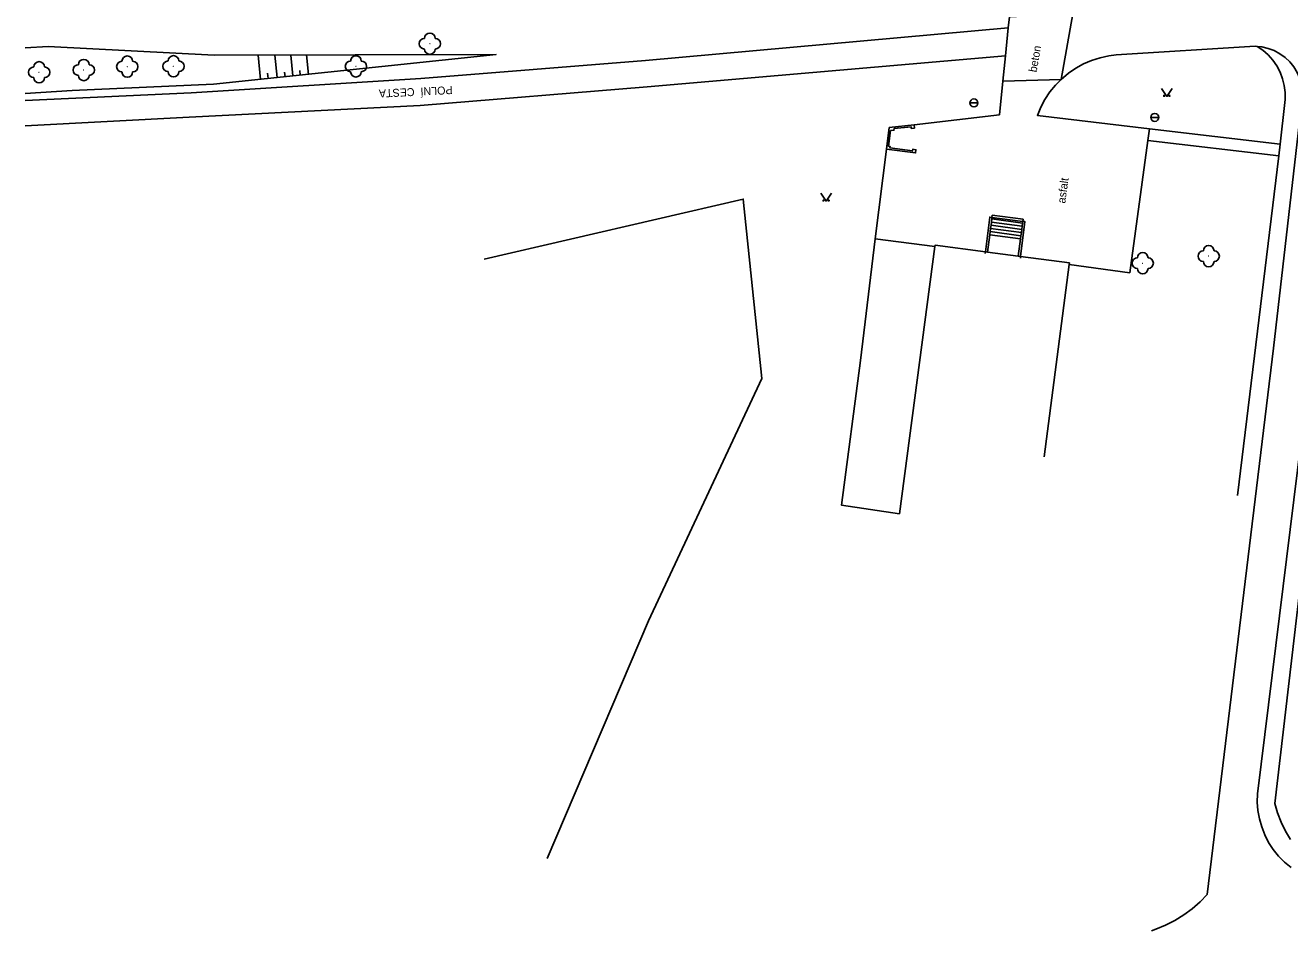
# Model space of a CAD drawing. Extents: x -536391 to -535419, y -1201788 to -1200779.
# Drawn here: x -535851.5 to -535733, y -1201700.2 to -1201615.3 of the extents above; entities that cross this region are included whole.
import ezdxf

# ---------------------------------------------------------------- set-up
doc = ezdxf.new("R2010")
doc.units = 0
for name, color, linetype in [('CIZÍ_PODZEM_POPIS', 7, 'Continuous'), ('DOPLŇ_POPISY', 7, 'Continuous'), ('KONEC_VEDENÍ', 7, 'Continuous'), ('POL_ZNAČKA_PRACOVNÍ', 7, 'Continuous'), ('SDEL_EON', 7, 'Continuous'), ('SDEL_EON_POPIS', 7, 'Continuous'), ('TECH_OCHR_PÁSMO_HRAN', 7, 'Continuous')]:
    doc.layers.add(name, color=color, linetype=linetype)

msp = doc.modelspace()

# ---------------------------------------------------------------- linework, layer by layer
at = {"layer": 'CIZÍ_PODZEM_POPIS'}
for p, q in [((-535762.935, -1201622.56), (-535762.185, -1201622.56)), ((-535745.975, -1201623.91), (-535745.225, -1201623.91))]:
    msp.add_line(p, q, dxfattribs=at)
for points in [[(-535851.47, -1201621.68), (-535847.09, -1201621.4), (-535833.82, -1201620.81), (-535807.34, -1201618.03), (-535833.76, -1201618.08), (-535849.31, -1201617.27), (-535851.47, -1201617.39)], [(-535770.74, -1201626.89), (-535770.49, -1201624.86), (-535768.16, -1201624.61)], [(-535768.16, -1201624.61), (-535768.13, -1201624.91), (-535768.43, -1201624.94), (-535768.44, -1201624.79), (-535770.04, -1201624.96), (-535770.06, -1201625.11), (-535770.37, -1201625.15), (-535770.56, -1201626.61), (-535770.41, -1201626.63), (-535770.43, -1201626.78), (-535768.31, -1201627.05), (-535768.29, -1201626.9), (-535767.99, -1201626.94), (-535768.03, -1201627.24), (-535770.74, -1201626.89)]]:
    msp.add_lwpolyline(points, dxfattribs=at)
for centre in [(-535762.56, -1201622.56), (-535745.6, -1201623.91)]:
    msp.add_circle(centre, 0.375, dxfattribs=at)
at = {"layer": 'DOPLŇ_POPISY'}
for points in [[(-535829.41, -1201620.35), (-535829.65, -1201618.07)], [(-535827.86, -1201620.18), (-535828.08, -1201618.07)], [(-535826.39, -1201620.03), (-535826.59, -1201618.07)], [(-535824.92, -1201619.88), (-535825.11, -1201618.06)], [(-535828.72, -1201620.27), (-535828.77, -1201619.76)], [(-535827.11, -1201620.11), (-535827.16, -1201619.66)], [(-535825.7, -1201619.96), (-535825.74, -1201619.52)]]:
    msp.add_lwpolyline(points, dxfattribs=at)
at = {"layer": 'KONEC_VEDENÍ'}
msp.add_lwpolyline([(-535808.46, -1201637.19), (-535784.18, -1201631.57), (-535782.44, -1201648.38), (-535793.05, -1201671.12), (-535802.54, -1201693.4)], dxfattribs=at)
for centre in [(-535813.55, -1201617), (-535850.17, -1201619.68), (-535845.99, -1201619.47), (-535841.91, -1201619.15), (-535837.58, -1201619.12), (-535820.48, -1201619.13), (-535746.73, -1201637.58), (-535740.55, -1201636.92)]:
    msp.add_circle(centre, 0.0005, dxfattribs=at)
for centre, start, end in [((-535813.55, -1201616.5), 0, 179.99999), ((-535814.05, -1201617), 89.99999, 269.99999), ((-535813.55, -1201617.5), 179.99999, 359.99999), ((-535813.05, -1201617), 270, 89.99999), ((-535850.17, -1201619.18), 0, 179.99999), ((-535845.99, -1201618.97), 0, 179.99999), ((-535842.41, -1201619.15), 89.99999, 269.99999), ((-535841.91, -1201618.65), 0, 179.99999), ((-535841.41, -1201619.15), 270, 89.99999), ((-535838.08, -1201619.12), 89.99999, 269.99999), ((-535837.58, -1201618.62), 0, 179.99999), ((-535837.08, -1201619.12), 270, 89.99999), ((-535820.98, -1201619.13), 89.99999, 269.99999), ((-535820.48, -1201618.63), 0, 179.99999), ((-535819.98, -1201619.13), 270, 89.99999), ((-535850.67, -1201619.68), 89.99999, 269.99999), ((-535849.67, -1201619.68), 270, 89.99999), ((-535846.49, -1201619.47), 89.99999, 269.99999), ((-535845.99, -1201619.97), 179.99999, 359.99999), ((-535845.49, -1201619.47), 270, 89.99999), ((-535841.91, -1201619.65), 179.99999, 359.99999), ((-535837.58, -1201619.62), 179.99999, 359.99999), ((-535820.48, -1201619.63), 179.99999, 359.99999), ((-535850.17, -1201620.18), 179.99999, 359.99999), ((-535746.73, -1201637.08), 0, 179.99999), ((-535741.05, -1201636.92), 89.99999, 269.99999), ((-535740.55, -1201636.42), 0, 179.99999), ((-535740.05, -1201636.92), 270, 89.99999), ((-535747.23, -1201637.58), 89.99999, 269.99999), ((-535746.23, -1201637.58), 270, 89.99999), ((-535740.55, -1201637.42), 179.99999, 359.99999), ((-535746.73, -1201638.08), 179.99999, 359.99999)]:
    msp.add_arc(centre, 0.5, start, end, dxfattribs=at)
at = {"layer": 'SDEL_EON'}
for points in [[(-535744.97, -1201621.19), (-535744.47, -1201621.94), (-535743.97, -1201621.19)], [(-535776.91, -1201631.01), (-535776.41, -1201631.76), (-535775.91, -1201631.01)]]:
    msp.add_lwpolyline(points, dxfattribs=at)
for centre in [(-535744.72, -1201621.89), (-535744.22, -1201621.89), (-535776.66, -1201631.71), (-535776.16, -1201631.71)]:
    msp.add_circle(centre, 0.05, dxfattribs=at)
at = {"layer": 'SDEL_EON_POPIS'}
for points in [[(-535769.52, -1201661.07), (-535766.21, -1201636.03)], [(-535766.21, -1201636.03), (-535766.19, -1201635.9), (-535761.48, -1201636.52)], [(-535761.48, -1201636.52), (-535761.28, -1201636.55)], [(-535761.28, -1201636.55), (-535758.4, -1201636.93)], [(-535758.4, -1201636.93), (-535758.18, -1201636.96)], [(-535758.18, -1201636.96), (-535753.6, -1201637.56), (-535753.62, -1201637.7)], [(-535753.62, -1201637.7), (-535755.97, -1201655.74)]]:
    msp.add_lwpolyline(points, dxfattribs=at)
at = {"layer": 'TECH_OCHR_PÁSMO_HRAN'}
for points in [[(-535759.33, -1201615.52), (-535759.23, -1201614.49), (-535753.27, -1201614.2)], [(-535753.27, -1201614.2), (-535754.38, -1201620.36)], [(-535759.33, -1201615.52), (-535793.35, -1201618.58), (-535814.41, -1201620.27), (-535835.91, -1201621.61), (-535851.47, -1201622.34)], [(-535759.6, -1201618.13), (-535759.33, -1201615.52)], [(-535754.38, -1201620.36), (-535753.69, -1201619.77), (-535753.01, -1201619.3), (-535752.28, -1201618.9), (-535751.52, -1201618.57), (-535750.73, -1201618.32), (-535749.91, -1201618.15), (-535749.22, -1201618.06), (-535736.18, -1201617.24), (-535736, -1201617.26)], [(-535736, -1201617.26), (-535735.58, -1201617.3), (-535734.99, -1201617.44), (-535734.42, -1201617.65), (-535733.89, -1201617.94), (-535733.39, -1201618.29), (-535732.95, -1201618.71), (-535732.57, -1201619.18), (-535732.25, -1201619.69), (-535732.01, -1201620.25), (-535731.84, -1201620.83), (-535731.74, -1201621.43), (-535731.73, -1201621.59), (-535734.49, -1201645.56), (-535740.68, -1201696.76), (-535741.36, -1201697.46), (-535742.1, -1201698.11), (-535742.89, -1201698.69), (-535743.72, -1201699.21), (-535744.59, -1201699.66), (-535745.5, -1201700.03), (-535745.91, -1201700.17)], [(-535733.86, -1201626.41), (-535733.41, -1201622.53), (-535733.38, -1201622.24), (-535733.38, -1201621.58), (-535733.46, -1201620.93), (-535733.62, -1201620.29), (-535733.85, -1201619.67), (-535734.16, -1201619.09), (-535734.54, -1201618.55), (-535734.97, -1201618.06), (-535735.47, -1201617.62), (-535736, -1201617.26)], [(-535759.6, -1201618.13), (-535793.17, -1201621.05), (-535814.47, -1201622.81), (-535836.12, -1201623.88), (-535851.47, -1201624.71)], [(-535759.84, -1201620.53), (-535759.6, -1201618.13)], [(-535768.16, -1201624.61), (-535760.16, -1201623.67), (-535759.84, -1201620.53)], [(-535754.38, -1201620.36), (-535759.84, -1201620.53)], [(-535746.11, -1201624.99), (-535756.61, -1201623.72), (-535756.29, -1201622.95), (-535755.9, -1201622.22), (-535755.44, -1201621.53), (-535754.91, -1201620.89), (-535754.38, -1201620.36)], [(-535746.11, -1201624.99), (-535746.26, -1201626.08)], [(-535733.86, -1201626.41), (-535746.11, -1201624.99)], [(-535771.81, -1201635.29), (-535770.74, -1201626.89)], [(-535746.26, -1201626.08), (-535747.95, -1201638.48), (-535753.62, -1201637.7)], [(-535733.99, -1201627.51), (-535746.26, -1201626.08)], [(-535733.99, -1201627.51), (-535733.86, -1201626.41)], [(-535733.99, -1201627.51), (-535737.84, -1201659.35)], [(-535760.86, -1201633.29), (-535761.07, -1201633.26), (-535761.48, -1201636.52)], [(-535760.99, -1201634.32), (-535760.95, -1201634.02)], [(-535760.95, -1201634.02), (-535760.91, -1201633.72)], [(-535760.95, -1201634.02), (-535758.07, -1201634.41)], [(-535760.91, -1201633.72), (-535760.88, -1201633.42)], [(-535760.91, -1201633.72), (-535758.03, -1201634.12)], [(-535760.88, -1201633.42), (-535760.86, -1201633.29)], [(-535760.88, -1201633.42), (-535757.99, -1201633.82)], [(-535760.86, -1201633.29), (-535760.84, -1201633.09), (-535757.94, -1201633.46), (-535757.97, -1201633.66)], [(-535757.97, -1201633.66), (-535760.86, -1201633.29)], [(-535758.18, -1201636.96), (-535757.77, -1201633.68), (-535757.97, -1201633.66)], [(-535758.03, -1201634.12), (-535758.07, -1201634.41)], [(-535757.99, -1201633.82), (-535758.03, -1201634.12)], [(-535757.97, -1201633.66), (-535757.99, -1201633.82)], [(-535769.52, -1201661.07), (-535774.96, -1201660.27), (-535773.2, -1201646.69), (-535771.81, -1201635.29)], [(-535766.21, -1201636.03), (-535771.81, -1201635.29)], [(-535761.28, -1201636.55), (-535761.07, -1201634.91)], [(-535761.07, -1201634.91), (-535761.03, -1201634.61)], [(-535761.07, -1201634.91), (-535758.19, -1201635.31)], [(-535761.03, -1201634.61), (-535760.99, -1201634.32)], [(-535761.03, -1201634.61), (-535758.15, -1201635.01)], [(-535760.99, -1201634.32), (-535758.11, -1201634.71)], [(-535758.19, -1201635.31), (-535758.4, -1201636.93)], [(-535758.15, -1201635.01), (-535758.19, -1201635.31)], [(-535758.11, -1201634.71), (-535758.15, -1201635.01)], [(-535758.07, -1201634.41), (-535758.11, -1201634.71)], [(-535761.48, -1201636.52), (-535761.5, -1201636.66)], [(-535758.2, -1201637.1), (-535758.18, -1201636.96)], [(-535732.83, -1201694.23), (-535733.44, -1201693.73), (-535734, -1201693.17), (-535734.5, -1201692.55), (-535734.93, -1201691.89), (-535735.29, -1201691.18), (-535735.58, -1201690.44), (-535735.8, -1201689.68), (-535735.94, -1201688.9), (-535735.99, -1201688.11), (-535735.97, -1201687.32), (-535730.84, -1201645.85)], [(-535729.43, -1201646.25), (-535734.36, -1201688.24), (-535734.1, -1201689.13), (-535733.76, -1201689.99), (-535733.35, -1201690.83), (-535732.87, -1201691.62)]]:
    msp.add_lwpolyline(points, dxfattribs=at)

# ---------------------------------------------------------------- texts
at = {"layer": 'POL_ZNAČKA_PRACOVNÍ'}
for s, rotation, p in [('beton', 79.78999, (-535756.69, -1201619.72)), ('POLNÍ  CESTA', 182.82997, (-535811.44, -1201620.97)), ('asfalt', 82.22002, (-535754, -1201632.01))]:
    msp.add_text(s, height=0.75, rotation=rotation, dxfattribs=at).set_placement(p)

doc.saveas('drawing.dxf')
